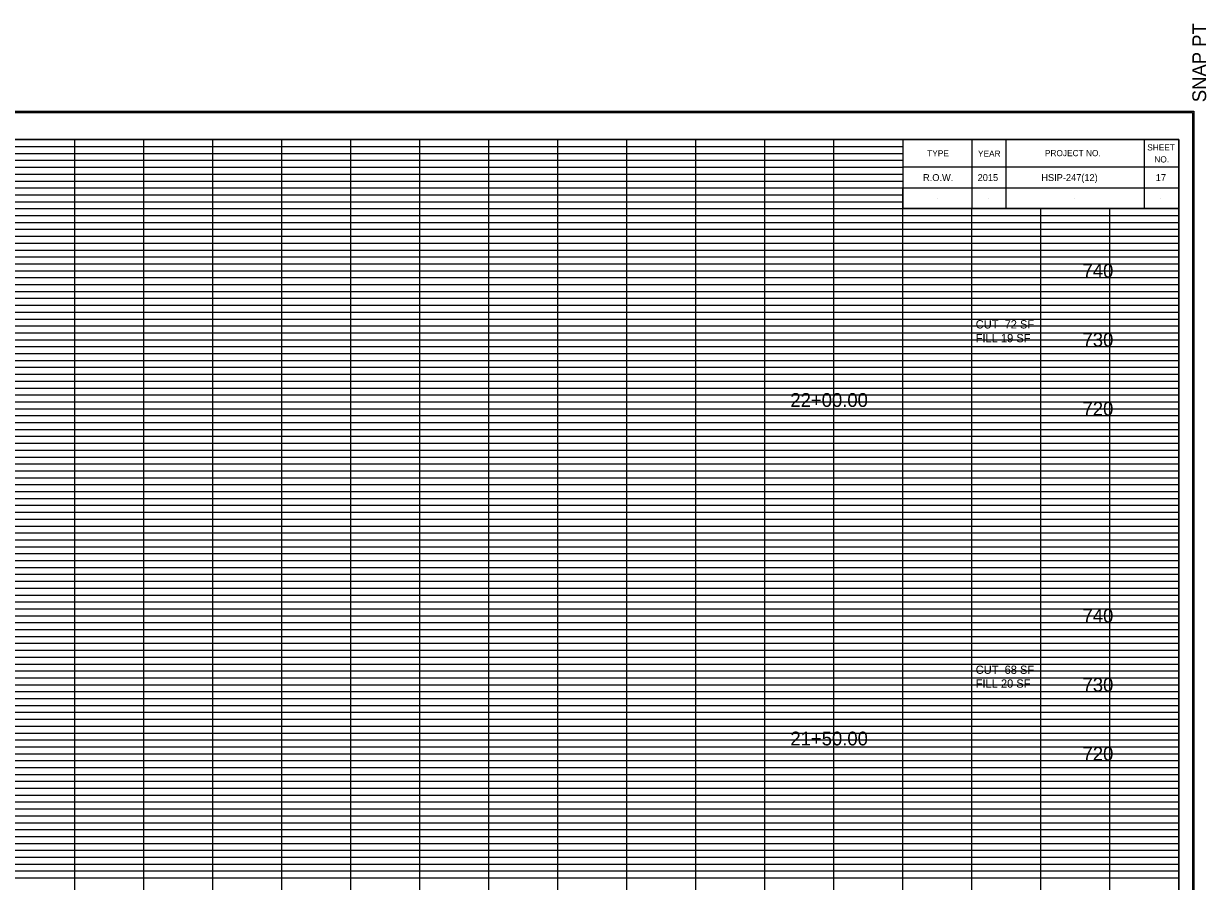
# Model space of a CAD drawing. Extents: x -200 to 1324, y -325 to 1497.
# Drawn here: x 1152.6 to 1324, y 1102.5 to 1226.8 of the extents above; entities that cross this region are included whole.
import ezdxf

# ---------------------------------------------------------------- set-up
doc = ezdxf.new("R2010")
doc.units = 0
for name, color, linetype in [('DESIGN - SCRATCH - User 1', 7, 'Continuous'), ('DESIGN - SHEET - Corner Text', 7, 'Continuous'), ('DESIGN - SHEET - Light Grid', 7, 'Continuous'), ('DESIGN - SHEET - Linework', 7, 'Continuous'), ('DESIGN - SHEET - Plot Shape', 7, 'Continuous'), ('DESIGN - TYPICAL - Text', 7, 'Continuous')]:
    doc.layers.add(name, color=color, linetype=linetype)

msp = doc.modelspace()

# ---------------------------------------------------------------- linework, layer by layer
at = {"layer": 'DESIGN - SCRATCH - User 1'}
for p, q in [((1285, 1204.5), (1285, 1204.5)), ((1292.4, 1204.5), (1292.4, 1204.5)), ((1304.9, 1204.5), (1304.9, 1204.5)), ((1317.4, 1204.5), (1317.4, 1204.5)), ((1285, 1201.5), (1285, 1201.5)), ((1292.4, 1201.5), (1292.4, 1201.5)), ((1304.9, 1201.5), (1304.9, 1201.5)), ((1317.4, 1201.5), (1317.4, 1201.5))]:
    msp.add_line(p, q, dxfattribs=at)
at = {"layer": 'DESIGN - SHEET - Light Grid'}
for p, q in [((1080, 1209), (1160, 1209)), ((1160, 1209), (1240, 1209)), ((1240, 1209), (1280, 1209)), ((1080, 1208), (1160, 1208)), ((1080, 1207), (1160, 1207)), ((1160, 1208), (1240, 1208)), ((1160, 1207), (1240, 1207)), ((1240, 1208), (1280, 1208)), ((1240, 1207), (1280, 1207)), ((1080, 1206), (1160, 1206)), ((1160, 1206), (1240, 1206)), ((1240, 1206), (1280, 1206)), ((1080, 1205), (1160, 1205)), ((1080, 1204), (1160, 1204)), ((1160, 1205), (1240, 1205)), ((1160, 1204), (1240, 1204)), ((1240, 1205), (1280, 1205)), ((1240, 1204), (1280, 1204)), ((1080, 1203), (1160, 1203)), ((1080, 1202), (1160, 1202)), ((1160, 1203), (1240, 1203)), ((1160, 1202), (1240, 1202)), ((1240, 1203), (1280, 1203)), ((1240, 1202), (1280, 1202)), ((1080, 1201), (1160, 1201)), ((1160, 1201), (1240, 1201)), ((1240, 1201), (1280, 1201)), ((1080, 1199), (1160, 1199)), ((1160, 1199), (1240, 1199)), ((1240, 1199), (1320, 1199)), ((1080, 1198), (1160, 1198)), ((1080, 1197), (1160, 1197)), ((1160, 1198), (1240, 1198)), ((1160, 1197), (1240, 1197)), ((1240, 1198), (1320, 1198)), ((1240, 1197), (1320, 1197)), ((1080, 1196), (1160, 1196)), ((1080, 1195), (1160, 1195)), ((1160, 1196), (1240, 1196)), ((1160, 1195), (1240, 1195)), ((1240, 1196), (1320, 1196)), ((1240, 1195), (1320, 1195)), ((1080, 1194), (1160, 1194)), ((1160, 1194), (1240, 1194)), ((1240, 1194), (1320, 1194)), ((1080, 1193), (1160, 1193)), ((1080, 1192), (1160, 1192)), ((1160, 1193), (1240, 1193)), ((1160, 1192), (1240, 1192)), ((1240, 1193), (1320, 1193)), ((1240, 1192), (1320, 1192)), ((1080, 1191), (1160, 1191)), ((1160, 1191), (1240, 1191)), ((1240, 1191), (1320, 1191)), ((1080, 1189), (1160, 1189)), ((1080, 1188), (1160, 1188)), ((1160, 1189), (1240, 1189)), ((1160, 1188), (1240, 1188)), ((1240, 1189), (1320, 1189)), ((1240, 1188), (1320, 1188)), ((1080, 1187), (1160, 1187)), ((1160, 1187), (1240, 1187)), ((1240, 1187), (1320, 1187)), ((1080, 1186), (1160, 1186)), ((1080, 1185), (1160, 1185)), ((1160, 1186), (1240, 1186)), ((1160, 1185), (1240, 1185)), ((1240, 1186), (1320, 1186)), ((1240, 1185), (1320, 1185)), ((1080, 1184), (1160, 1184)), ((1080, 1183), (1160, 1183)), ((1160, 1184), (1240, 1184)), ((1160, 1183), (1240, 1183)), ((1240, 1184), (1320, 1184)), ((1240, 1183), (1320, 1183)), ((1080, 1182), (1160, 1182)), ((1160, 1182), (1240, 1182)), ((1240, 1182), (1320, 1182)), ((1080, 1181), (1160, 1181)), ((1160, 1181), (1240, 1181)), ((1240, 1181), (1320, 1181)), ((1080, 1179), (1160, 1179)), ((1080, 1178), (1160, 1178)), ((1160, 1179), (1240, 1179)), ((1160, 1178), (1240, 1178)), ((1240, 1179), (1320, 1179)), ((1240, 1178), (1320, 1178)), ((1080, 1177), (1160, 1177)), ((1080, 1176), (1160, 1176)), ((1160, 1177), (1240, 1177)), ((1160, 1176), (1240, 1176)), ((1240, 1177), (1320, 1177)), ((1240, 1176), (1320, 1176)), ((1080, 1175), (1160, 1175)), ((1160, 1175), (1240, 1175)), ((1240, 1175), (1320, 1175)), ((1080, 1174), (1160, 1174)), ((1080, 1173), (1160, 1173)), ((1160, 1174), (1240, 1174)), ((1160, 1173), (1240, 1173)), ((1240, 1174), (1320, 1174)), ((1240, 1173), (1320, 1173)), ((1080, 1172), (1160, 1172)), ((1080, 1171), (1160, 1171)), ((1160, 1172), (1240, 1172)), ((1160, 1171), (1240, 1171)), ((1240, 1172), (1320, 1172)), ((1240, 1171), (1320, 1171)), ((1080, 1169), (1160, 1169)), ((1080, 1168), (1160, 1168)), ((1160, 1169), (1240, 1169)), ((1160, 1168), (1240, 1168)), ((1240, 1169), (1320, 1169)), ((1240, 1168), (1320, 1168)), ((1080, 1167), (1160, 1167)), ((1080, 1166), (1160, 1166)), ((1160, 1167), (1240, 1167)), ((1160, 1166), (1240, 1166)), ((1240, 1167), (1320, 1167)), ((1240, 1166), (1320, 1166)), ((1080, 1165), (1160, 1165)), ((1080, 1164), (1160, 1164)), ((1160, 1165), (1240, 1165)), ((1160, 1164), (1240, 1164)), ((1240, 1165), (1320, 1165)), ((1240, 1164), (1320, 1164)), ((1080, 1163), (1160, 1163)), ((1160, 1163), (1240, 1163)), ((1240, 1163), (1320, 1163)), ((1080, 1162), (1160, 1162)), ((1080, 1161), (1160, 1161)), ((1160, 1162), (1240, 1162)), ((1160, 1161), (1240, 1161)), ((1240, 1162), (1320, 1162)), ((1240, 1161), (1320, 1161)), ((1080, 1159), (1160, 1159)), ((1160, 1159), (1240, 1159)), ((1240, 1159), (1320, 1159)), ((1080, 1158), (1160, 1158)), ((1160, 1158), (1240, 1158)), ((1240, 1158), (1320, 1158)), ((1080, 1157), (1160, 1157)), ((1080, 1156), (1160, 1156)), ((1160, 1157), (1240, 1157)), ((1160, 1156), (1240, 1156)), ((1240, 1157), (1320, 1157)), ((1240, 1156), (1320, 1156)), ((1080, 1155), (1160, 1155)), ((1080, 1154), (1160, 1154)), ((1160, 1155), (1240, 1155)), ((1160, 1154), (1240, 1154)), ((1240, 1155), (1320, 1155)), ((1240, 1154), (1320, 1154)), ((1080, 1153), (1160, 1153)), ((1080, 1152), (1160, 1152)), ((1160, 1153), (1240, 1153)), ((1160, 1152), (1240, 1152)), ((1240, 1153), (1320, 1153)), ((1240, 1152), (1320, 1152)), ((1080, 1151), (1160, 1151)), ((1160, 1151), (1240, 1151)), ((1240, 1151), (1320, 1151)), ((1080, 1149), (1160, 1149)), ((1160, 1149), (1240, 1149)), ((1240, 1149), (1320, 1149)), ((1080, 1148), (1160, 1148)), ((1080, 1147), (1160, 1147)), ((1160, 1148), (1240, 1148)), ((1160, 1147), (1240, 1147)), ((1240, 1148), (1320, 1148)), ((1240, 1147), (1320, 1147)), ((1080, 1146), (1160, 1146)), ((1160, 1146), (1240, 1146)), ((1240, 1146), (1320, 1146)), ((1080, 1145), (1160, 1145)), ((1080, 1144), (1160, 1144)), ((1160, 1145), (1240, 1145)), ((1160, 1144), (1240, 1144)), ((1240, 1145), (1320, 1145)), ((1240, 1144), (1320, 1144)), ((1080, 1143), (1160, 1143)), ((1080, 1142), (1160, 1142)), ((1160, 1143), (1240, 1143)), ((1160, 1142), (1240, 1142)), ((1240, 1143), (1320, 1143)), ((1240, 1142), (1320, 1142)), ((1080, 1141), (1160, 1141)), ((1160, 1141), (1240, 1141)), ((1240, 1141), (1320, 1141)), ((1080, 1139), (1160, 1139)), ((1160, 1139), (1240, 1139)), ((1240, 1139), (1320, 1139)), ((1080, 1138), (1160, 1138)), ((1080, 1137), (1160, 1137)), ((1160, 1138), (1240, 1138)), ((1160, 1137), (1240, 1137)), ((1240, 1138), (1320, 1138)), ((1240, 1137), (1320, 1137)), ((1080, 1136), (1160, 1136)), ((1080, 1135), (1160, 1135)), ((1160, 1136), (1240, 1136)), ((1160, 1135), (1240, 1135)), ((1240, 1136), (1320, 1136)), ((1240, 1135), (1320, 1135)), ((1080, 1134), (1160, 1134)), ((1160, 1134), (1240, 1134)), ((1240, 1134), (1320, 1134)), ((1080, 1133), (1160, 1133)), ((1080, 1132), (1160, 1132)), ((1160, 1133), (1240, 1133)), ((1160, 1132), (1240, 1132)), ((1240, 1133), (1320, 1133)), ((1240, 1132), (1320, 1132)), ((1080, 1131), (1160, 1131)), ((1160, 1131), (1240, 1131)), ((1240, 1131), (1320, 1131)), ((1080, 1129), (1160, 1129)), ((1080, 1128), (1160, 1128)), ((1160, 1129), (1240, 1129)), ((1160, 1128), (1240, 1128)), ((1240, 1129), (1320, 1129)), ((1240, 1128), (1320, 1128)), ((1080, 1127), (1160, 1127)), ((1160, 1127), (1240, 1127)), ((1240, 1127), (1320, 1127)), ((1080, 1126), (1160, 1126)), ((1080, 1125), (1160, 1125)), ((1160, 1126), (1240, 1126)), ((1160, 1125), (1240, 1125)), ((1240, 1126), (1320, 1126)), ((1240, 1125), (1320, 1125)), ((1080, 1124), (1160, 1124)), ((1080, 1123), (1160, 1123)), ((1160, 1124), (1240, 1124)), ((1160, 1123), (1240, 1123)), ((1240, 1124), (1320, 1124)), ((1240, 1123), (1320, 1123)), ((1080, 1122), (1160, 1122)), ((1160, 1122), (1240, 1122)), ((1240, 1122), (1320, 1122)), ((1080, 1121), (1160, 1121)), ((1160, 1121), (1240, 1121)), ((1240, 1121), (1320, 1121)), ((1080, 1119), (1160, 1119)), ((1080, 1118), (1160, 1118)), ((1160, 1119), (1240, 1119)), ((1160, 1118), (1240, 1118)), ((1240, 1119), (1320, 1119)), ((1240, 1118), (1320, 1118)), ((1080, 1117), (1160, 1117)), ((1080, 1116), (1160, 1116)), ((1160, 1117), (1240, 1117)), ((1160, 1116), (1240, 1116)), ((1240, 1117), (1320, 1117)), ((1240, 1116), (1320, 1116)), ((1080, 1115), (1160, 1115)), ((1160, 1115), (1240, 1115)), ((1240, 1115), (1320, 1115)), ((1080, 1114), (1160, 1114)), ((1080, 1113), (1160, 1113)), ((1160, 1114), (1240, 1114)), ((1160, 1113), (1240, 1113)), ((1240, 1114), (1320, 1114)), ((1240, 1113), (1320, 1113)), ((1080, 1112), (1160, 1112)), ((1080, 1111), (1160, 1111)), ((1160, 1112), (1240, 1112)), ((1160, 1111), (1240, 1111)), ((1240, 1112), (1320, 1112)), ((1240, 1111), (1320, 1111)), ((1080, 1109), (1160, 1109)), ((1080, 1108), (1160, 1108)), ((1160, 1109), (1240, 1109)), ((1160, 1108), (1240, 1108)), ((1240, 1109), (1320, 1109)), ((1240, 1108), (1320, 1108)), ((1080, 1107), (1160, 1107)), ((1080, 1106), (1160, 1106)), ((1160, 1107), (1240, 1107)), ((1160, 1106), (1240, 1106)), ((1240, 1107), (1320, 1107)), ((1240, 1106), (1320, 1106)), ((1080, 1105), (1160, 1105)), ((1080, 1104), (1160, 1104)), ((1160, 1105), (1240, 1105)), ((1160, 1104), (1240, 1104)), ((1240, 1105), (1320, 1105)), ((1240, 1104), (1320, 1104)), ((1080, 1103), (1160, 1103)), ((1160, 1103), (1240, 1103)), ((1240, 1103), (1320, 1103))]:
    msp.add_line(p, q, dxfattribs=at)
at = {"layer": 'DESIGN - SHEET - Linework'}
for p, q in [((981.77, 1214.14), (1322.17, 1214.14)), ((1322.17, 1214.14), (1322.17, 995.86)), ((1160, 1000), (1160, 1210)), ((1170, 1000), (1170, 1210)), ((1180, 1000), (1180, 1210)), ((1190, 1000), (1190, 1210)), ((1200, 1000), (1200, 1210)), ((1210, 1000), (1210, 1210)), ((1220, 1000), (1220, 1210)), ((1230, 1000), (1230, 1210)), ((1240, 1000), (1240, 1210)), ((1250, 1000), (1250, 1210)), ((1260, 1000), (1260, 1210)), ((1270, 1000), (1270, 1210)), ((1000, 1200), (1280, 1200)), ((1280, 1000), (1280, 1200)), ((1290, 1000), (1290, 1200)), ((1300, 1000), (1300, 1200)), ((1310, 1000), (1310, 1200)), ((1000, 1190), (1320, 1190)), ((1000, 1180), (1320, 1180)), ((1000, 1170), (1320, 1170)), ((1000, 1160), (1320, 1160)), ((1000, 1150), (1320, 1150)), ((1000, 1140), (1320, 1140)), ((1000, 1130), (1320, 1130)), ((1000, 1120), (1320, 1120)), ((1000, 1110), (1320, 1110))]:
    msp.add_line(p, q, dxfattribs=at)
for points in [[(1000, 1210), (1000, 1000), (1320, 1000), (1320, 1210), (1000, 1210)], [(1280, 1210), (1280, 1200), (1320, 1200), (1320, 1210), (1315, 1210), (1315, 1200), (1295, 1200), (1295, 1210), (1290, 1210), (1290, 1200), (1320, 1200), (1280, 1200), (1280, 1203), (1320, 1203), (1320, 1206), (1280, 1206)]]:
    msp.add_lwpolyline(points, dxfattribs=at)
at = {"layer": 'DESIGN - SHEET - Plot Shape'}
for points in [[(981.97, 1213.94), (1321.97, 1213.94), (1321.97, 996.06), (981.97, 996.06)], [(991.5, 1210), (1320, 1210), (1320, 997.5), (991.5, 997.5)]]:
    msp.add_lwpolyline(points, close=True, dxfattribs=at)

# ---------------------------------------------------------------- texts
at = {"layer": 'DESIGN - SHEET - Corner Text'}
msp.add_text('  SNAP PT', height=2, rotation=90, dxfattribs=at).set_placement((1323.97, 1213.94))
for s, height, p in [('TYPE', 0.9, (1283.54, 1207.56)), ('PROJECT NO.', 0.9, (1300.6, 1207.6)), ('SHEET', 0.9, (1315.43, 1208.43)), ('YEAR', 0.9, (1290.9, 1207.52)), ('NO.', 0.9, (1316.46, 1206.69)), ('R.O.W.', 1, (1282.94, 1204)), ('2015', 1, (1290.85, 1204)), ('HSIP-247(12)', 1, (1300.08, 1204)), ('17', 1, (1316.67, 1204))]:
    msp.add_text(s, height=height, dxfattribs=at).set_placement(p)
at = {"layer": 'DESIGN - TYPICAL - Text'}
for s, height, p in [('     740     ', 2, (1302.34, 1190)), ('CUT  72 SF', 1.2, (1290.57, 1182.63)), ('FILL 19 SF', 1.2, (1290.57, 1180.63)), ('     730     ', 2, (1302.34, 1180)), ('     22+00.00     ', 2, (1260, 1171.26)), ('     720     ', 2, (1302.34, 1170)), ('     740     ', 2, (1302.34, 1140)), ('CUT  68 SF', 1.2, (1290.57, 1132.57)), ('FILL 20 SF', 1.2, (1290.57, 1130.57)), ('     730     ', 2, (1302.34, 1130)), ('     21+50.00     ', 2, (1260, 1122.2)), ('     720     ', 2, (1302.34, 1120))]:
    msp.add_text(s, height=height, dxfattribs=at).set_placement(p)

doc.saveas('drawing.dxf')
